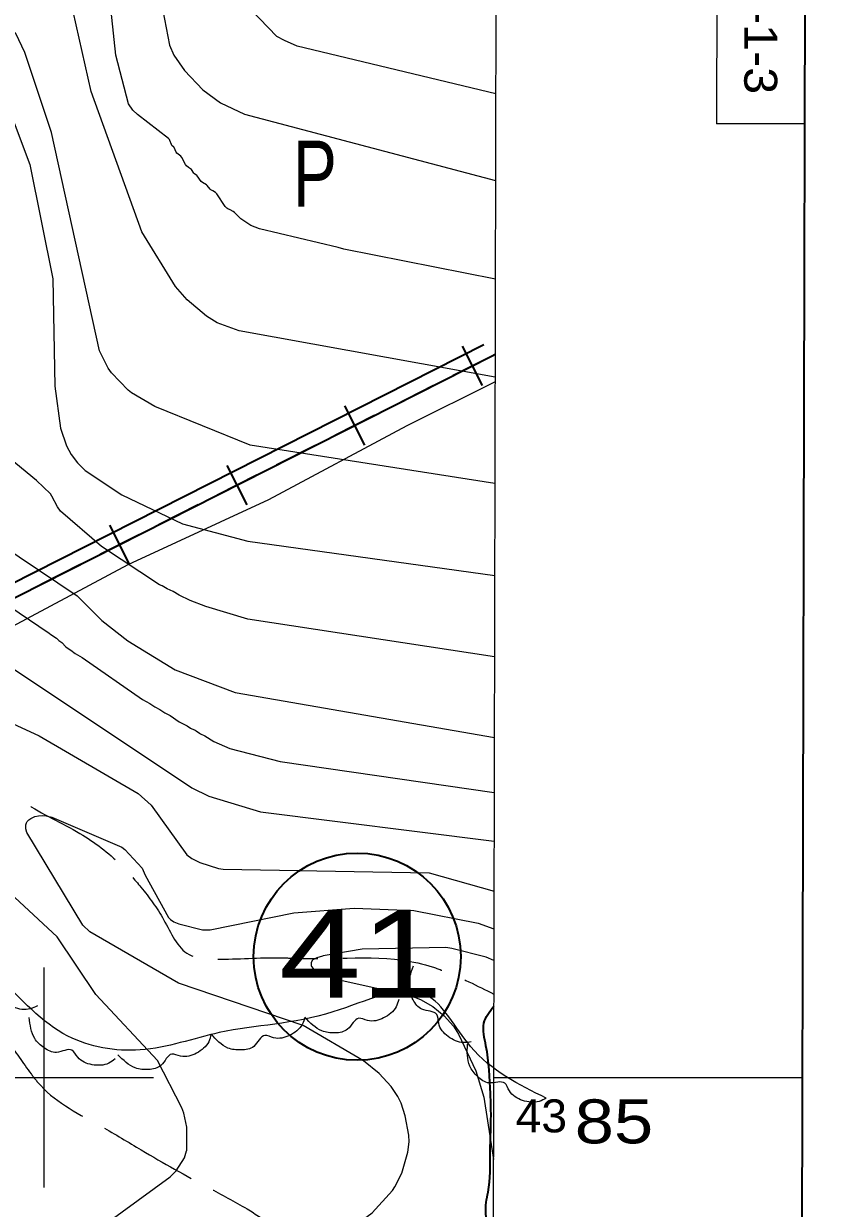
# Model space of a CAD drawing. Extents: x 480269 to 484877, y 4383588 to 4386804.
# Drawn here: x 483995.4 to 484176.2, y 4384970.2 to 4385239.6 of the extents above; entities that cross this region are included whole.
import ezdxf
from ezdxf.enums import TextEntityAlignment as Align

# ---------------------------------------------------------------- set-up
doc = ezdxf.new("R2010")
doc.units = 0
doc.header["$LTSCALE"] = 3.8
doc.linetypes.add('DOTTED', pattern=[1.5, 0.3, -1.2])
doc.linetypes.add('LONG_DASHED', pattern=[7.5, 6, -1.5])
for name, color, linetype, lineweight in [('1', 7, 'Continuous', 13), ('13', 7, 'Continuous', 25), ('2', 7, 'DOTTED', 13), ('27', 7, 'Continuous', 25), ('34', 7, 'Continuous', 35), ('38', 7, 'Continuous', 25), ('51', 7, 'Continuous', 13), ('6', 7, 'Continuous', 35), ('8', 7, 'Continuous', 25), ('9', 7, 'Continuous', 13)]:
    doc.layers.add(name, color=color, linetype=linetype, lineweight=lineweight)
doc.layers.add('31', color=7, linetype='Continuous')

msp = doc.modelspace()

# ---------------------------------------------------------------- linework, layer by layer
at = {"layer": '1'}
for p, q in [((484173.1, 4385216.78), (484153.1, 4385216.82)), ((484000, 4385025), (484000, 4384975)), ((483975, 4385000), (484025, 4385000)), ((484102.37, 4385000), (484172.58, 4385000))]:
    msp.add_line(p, q, dxfattribs=at)
at = {"layer": '1', "lineweight": 35}
msp.add_lwpolyline([(480458.83, 4386528.21), (484176.23, 4386519.28), (484170.33, 4384064.28), (480452.93, 4384073.22)], close=True, dxfattribs=at)
at = {"layer": '1'}
msp.add_lwpolyline([(480529.1, 4386456.6), (484105.5, 4386448.1), (484100.5, 4384135.8), (480523.1, 4384144.4)], close=True, dxfattribs=at)
msp.add_lwpolyline([(484173.46, 4385366.78), (484153.46, 4385366.82), (484153.1, 4385216.82)], dxfattribs=at)
at = {"layer": '27'}
for points in [[(484114.34, 4384995.29), (484097.11, 4385007.04), (484086.93, 4385018.79), (484065.79, 4385014.87), (484039.96, 4385010.17), (484021.95, 4385006.26), (484005.51, 4385009.39), (483989.85, 4385022.71), (483953.05, 4385049.34), (483919.38, 4385069.7), (483866.14, 4385090.85), (483825.42, 4385101.82), (483759.65, 4385127.67), (483723.64, 4385129.24)], [(483998.56, 4385016.28), (483996.93, 4385015.58), (483993.15, 4385015.96), (483990.25, 4385018.24), (483989.27, 4385020.04), (483985.72, 4385020.22), (483983.15, 4385021.74), (483981.43, 4385024.23), (483981.11, 4385029.18)], [(484097.29, 4385008.11), (484095.53, 4385007.9), (484092.01, 4385009.31), (484089.86, 4385012.32), (484089.43, 4385014.32), (484086.06, 4385015.48), (484084.03, 4385017.66), (484083.07, 4385020.53), (484084.15, 4385025.37)], [(484080.78, 4385017.7), (484080.17, 4385016.03), (484077.33, 4385013.52), (484073.68, 4385012.94), (484071.7, 4385013.45), (484069.15, 4385010.97), (484066.29, 4385010.12), (484063.3, 4385010.55), (484059.45, 4385013.68)], [(484016.27, 4385004.21), (484014.79, 4385003.22), (484011.01, 4385002.89), (484007.74, 4385004.59), (484006.44, 4385006.18), (484002.92, 4385005.69), (484000.11, 4385006.71), (483997.96, 4385008.83), (483996.72, 4385013.64)], [(484059.44, 4385013.72), (484058.83, 4385012.05), (484055.97, 4385009.56), (484052.32, 4385009.01), (484050.34, 4385009.53), (484047.78, 4385007.06), (484044.91, 4385006.23), (484041.92, 4385006.68), (484038.09, 4385009.84)], [(484038.1, 4385009.8), (484037.55, 4385008.11), (484034.78, 4385005.52), (484031.15, 4385004.84), (484029.15, 4385005.29), (484026.68, 4385002.73), (484023.84, 4385001.8), (484020.84, 4385002.15), (484016.9, 4385005.16)], [(484114.34, 4384995.29), (484112.73, 4384994.53), (484108.95, 4384994.77), (484105.96, 4384996.94), (484104.91, 4384998.7), (484101.36, 4384998.74), (484098.74, 4385000.17), (484096.93, 4385002.59), (484096.42, 4385007.52)]]:
    msp.add_spline(points, degree=3, dxfattribs=at)
at = {"layer": '34'}
for p, q in [((484102, 4385164), (484093.09, 4385159.49)), ((484099.81, 4385157.29), (484095.29, 4385166.21)), ((484102.72, 4385164.38), (484102, 4385164)), ((484102.72, 4385164.38), (484102, 4385164)), ((484088.63, 4385157.23), (484079.7, 4385152.71)), ((484073.05, 4385143.74), (484068.53, 4385152.66)), ((484075.25, 4385150.46), (484066.33, 4385145.94)), ((484061.87, 4385143.68), (484052.95, 4385139.17)), ((484046.29, 4385130.19), (484041.78, 4385139.11)), ((484048.5, 4385136.91), (484039.57, 4385132.39)), ((484035.11, 4385130.14), (484026.19, 4385125.62)), ((484019.54, 4385116.65), (484015.02, 4385125.57)), ((484021.74, 4385123.37), (484012.82, 4385118.85)), ((484008.36, 4385116.59), (483999.44, 4385112.07))]:
    msp.add_line(p, q, dxfattribs=at)
for points in [[(484100.12, 4385166.55), (483464.12, 4384844.55), (483456.6, 4384851.12)], [(484100.12, 4385166.55), (483464.12, 4384844.55), (483456.6, 4384851.12)], [(484102, 4385164), (483466, 4384842), (483458.48, 4384848.57)]]:
    msp.add_lwpolyline(points, dxfattribs=at)
at = {"layer": '38', "linetype": 'LONG_DASHED'}
for points in [[(483942.39, 4385122.34), (483952.45, 4385095.91), (483958.21, 4385088.21), (483962.69, 4385083.26), (483973.19, 4385074.99), (483980.96, 4385070.43), (483992.37, 4385064.77), (483995.68, 4385062.46), (484008.26, 4385055.45), (484017.51, 4385048.36), (484022.13, 4385043.23), (484027.29, 4385035.86), (484033.07, 4385027.94), (484039.2, 4385026.88), (484053.86, 4385027.2), (484058.16, 4385027.05), (484086.84, 4385025.6), (484090.95, 4385024.22), (484102.41, 4385018.95)], [(483895.65, 4385049.41), (483901.31, 4385046.22), (483904.97, 4385044), (483908.38, 4385043.58), (483917.3, 4385045.07), (483924.03, 4385045.27), (483935.07, 4385044.92), (483947.94, 4385042.69), (483964.34, 4385037.18), (483972.2, 4385033.41), (483980.56, 4385025.17), (483986.43, 4385015.59), (483991.76, 4385008.34), (483997.14, 4385000.8), (483999.32, 4384998.13), (484013.2, 4384988.81), (484022.21, 4384983.5), (484037.49, 4384974.93), (484046.27, 4384970.1), (484052.18, 4384966.26), (484063.24, 4384958.28), (484072.05, 4384951.59)]]:
    msp.add_spline(points, degree=3, dxfattribs=at)
at = {"layer": '51'}
msp.add_lwpolyline([(484102.71, 4385158.17), (484082.61, 4385148.15), (484051.15, 4385131.29), (484019.11, 4385116.52), (483992.79, 4385102.45), (483964.38, 4385087.36), (483957.17, 4385084.5)], dxfattribs=at)
at = {"layer": '6'}
msp.add_circle((484071.32, 4385027.45), 23.55, dxfattribs=at)
msp.add_spline([(484072.71, 4384951.59), (484076.5, 4384951.46), (484085.91, 4384953.29), (484092.76, 4384955.65), (484097.86, 4384958.35), (484100.69, 4384966.27), (484100.68, 4384971.57), (484101.12, 4384973.91), (484101.59, 4384983.01), (484101.76, 4384992.72), (484101.64, 4384996.31), (484100.61, 4385007.16), (484100.17, 4385012.34), (484102.4, 4385016.18)], degree=3, dxfattribs=at)
at = {"layer": '8'}
for points in [[(484102.66, 4385135.05), (484046.95, 4385143.74), (484025.31, 4385152.49), (484019.95, 4385155.66), (484019.19, 4385156.21), (484015.46, 4385160.21), (484014.7, 4385161.26), (484012.69, 4385165.2), (484001.76, 4385214.82), (483995.69, 4385233.03), (483993.63, 4385237.36), (483992.77, 4385238.34), (483990.76, 4385239.88)], [(483967.81, 4385109.7), (484033.71, 4385065.86), (484037.56, 4385063.92), (484049.36, 4385060.39), (484102.48, 4385053.67)]]:
    msp.add_lwpolyline(points, dxfattribs=at)
at = {"layer": '9'}
msp.add_line((484102.76, 4385181.49), (484068.3, 4385188.32), dxfattribs=at)
for points in [[(484102.71, 4385159.22), (484044.49, 4385169.71), (484039.47, 4385171.58), (484037.02, 4385173.05), (484032.68, 4385176.75), (484029.98, 4385179.78), (484022.32, 4385192.2), (484010.83, 4385224.15), (484003.97, 4385254.56)], [(484068.3, 4385188.32), (484066.96, 4385188.71), (484049.1, 4385192.91), (484047.12, 4385193.69), (484044.89, 4385195.16), (484043.4, 4385196.65), (484043.14, 4385196.85), (484042.42, 4385197.27), (484041.91, 4385197.47), (484041.66, 4385197.62), (484041.29, 4385197.98), (484039.39, 4385200.85), (484039.07, 4385201.21), (484038.52, 4385201.57), (484038.05, 4385201.8), (484037.84, 4385201.97), (484037.23, 4385202.75), (484037.02, 4385202.92), (484036.1, 4385203.44), (484035.84, 4385203.68), (484034.93, 4385204.95), (484034.84, 4385205.05), (484034.31, 4385205.43), (484034.18, 4385205.59), (484033.61, 4385206.41), (484033.41, 4385206.59), (484032.98, 4385206.86), (484032.51, 4385207.21), (484032.27, 4385207.53), (484031.42, 4385209.14), (484031.18, 4385209.47), (484030.32, 4385210.14), (484030.14, 4385210.35), (484029.65, 4385211.37), (484029.6, 4385211.45), (484029.17, 4385211.88), (484029.07, 4385212.07), (484028.71, 4385213.01), (484028.6, 4385213.2), (484028.39, 4385213.42), (484021.35, 4385218.89), (484020.32, 4385219.89), (484019.28, 4385221.31), (484016.42, 4385232.39), (484014.08, 4385254.57)], [(484102.85, 4385223.6), (484057.68, 4385234.48), (484054.81, 4385235.74), (484053.02, 4385236.67), (484039.17, 4385251.11)], [(484025.95, 4385248.56), (484028.62, 4385234.66), (484029.59, 4385232.37), (484032.04, 4385228.88), (484036.21, 4385224.54), (484040.25, 4385221.56), (484045.66, 4385218.99), (484102.81, 4385203.94)], [(483992.6, 4385218.8), (483996.84, 4385207.58), (484002.1, 4385181.53), (484002.52, 4385157.16), (484003.83, 4385147.59), (484005.2, 4385143.6), (484006.29, 4385141.63), (484007.72, 4385139.72), (484009.42, 4385138), (484017.75, 4385132.46), (484031.55, 4385125.87), (484046.45, 4385121.91), (484102.62, 4385114.11)], [(484102.58, 4385095.62), (484046.46, 4385104.16), (484036.88, 4385107.09), (484033.34, 4385108.45), (484030.84, 4385109.65), (484029.45, 4385110.48), (484028.06, 4385111.04), (484026.95, 4385111.73), (484026.33, 4385112), (484013.18, 4385120.72), (484003.81, 4385128.72), (484003.13, 4385129.75), (484001.89, 4385132.13), (484001.54, 4385132.68), (483998.4, 4385135.7), (483992.36, 4385140.64)], [(483985.53, 4385124.27), (484007.59, 4385109.51), (484013.24, 4385103.86), (484019.18, 4385099.22), (484029.89, 4385092.63), (484043.53, 4385087.47), (484102.54, 4385077.28)], [(483969.62, 4385122.4), (484001.28, 4385100.96), (484001.6, 4385100.7), (484002.88, 4385099.87), (484003.46, 4385099.32), (484004.13, 4385098.84), (484005.07, 4385097.86), (484005.31, 4385097.66)], [(483941.08, 4385098.8), (483941.36, 4385098.99), (483941.92, 4385099.2), (483942.73, 4385099.4), (483942.86, 4385099.42), (483944.07, 4385099.51), (483945.44, 4385099.46), (483945.47, 4385099.47), (483947.42, 4385099.17), (483951.55, 4385098.03), (483951.57, 4385098.03), (483975.99, 4385088.91), (483982.84, 4385085.08), (483999, 4385077.66), (484021.46, 4385064.54), (484024.45, 4385061.9), (484032.59, 4385050.6), (484033.74, 4385049.77), (484035.54, 4385048.88), (484039.76, 4385047.5), (484040.84, 4385047.35), (484087.73, 4385046.53), (484102.46, 4385042.34)], [(484004.15, 4384959.43), (484028.77, 4384977.43), (484030.13, 4384978.73), (484032.05, 4384981.75), (484032.51, 4384983.29), (484032.54, 4384983.31), (484032.57, 4384988.65), (484031.89, 4384991.86), (484031.45, 4384993.1), (484025.86, 4385003.85), (484011.9, 4385018.81), (484003.09, 4385031.95), (483949.37, 4385081.77), (483947.94, 4385083.28), (483944.1, 4385088.45), (483940.57, 4385094.75), (483940.17, 4385096), (483940.15, 4385096.18), (483940.12, 4385097), (483940.19, 4385097.53), (483940.29, 4385097.83), (483940.63, 4385098.35), (483941.08, 4385098.8)], [(484005.31, 4385097.66), (484006.21, 4385097.1), (484007.14, 4385096.35), (484008.72, 4385095.45), (484022.48, 4385085.94), (484024.14, 4385085.02), (484025.3, 4385084.25), (484026.46, 4385083.64), (484027.53, 4385082.9), (484028.76, 4385082.25), (484030.83, 4385080.82), (484032.64, 4385079.94), (484033.42, 4385079.4), (484033.53, 4385079.34), (484034.49, 4385078.91), (484034.71, 4385078.79), (484035.43, 4385078.24), (484035.66, 4385078.11), (484036.66, 4385077.69), (484038.69, 4385076.38), (484042.38, 4385074.79), (484053.83, 4385071.81), (484102.51, 4385064.79)], [(484083.12, 4384985.37), (484083.06, 4384986.85), (484082.27, 4384991.23), (484081.32, 4384994.17), (484080.58, 4384995.65), (484079.02, 4384997.94), (484076.32, 4385000.88), (484072.76, 4385003.75), (484059.02, 4385011.81), (484030.65, 4385021.43), (484010.53, 4385033.11), (484008.9, 4385034.63), (483996.18, 4385055.68), (483995.97, 4385056.49), (483995.92, 4385056.87), (483995.95, 4385057.44), (483996.12, 4385057.9), (483996.26, 4385058.14), (483996.61, 4385058.54), (483997.06, 4385058.88), (483997.35, 4385059.04), (483997.96, 4385059.28), (483998.83, 4385059.46), (483999.78, 4385059.51), (484000.56, 4385059.45), (484001.82, 4385059.2), (484017.8, 4385052.37), (484018.49, 4385051.78), (484022.43, 4385047.53), (484023.11, 4385046.01), (484028.43, 4385036.33), (484028.84, 4385035.93), (484029.6, 4385035.38), (484030.73, 4385034.89), (484036.16, 4385033.54), (484037.9, 4385033.54), (484056.94, 4385037.42), (484070.67, 4385038.5), (484084.21, 4385037.95), (484098.83, 4385035.03), (484102.44, 4385033.78)], [(484102.43, 4385026.56), (484100.65, 4385027.35), (484092.87, 4385029.32), (484091.46, 4385029.55), (484072.46, 4385029.13), (484063.57, 4385027.62), (484063.43, 4385027.58), (484062.17, 4385027.16), (484061.38, 4385026.81), (484061.22, 4385026.69), (484061.09, 4385026.57), (484060.82, 4385026.05), (484060.84, 4385025.5), (484060.88, 4385025.36), (484060.95, 4385025.22), (484061.32, 4385024.76), (484061.97, 4385024.15), (484062.07, 4385024.08), (484063.15, 4385023.53), (484063.18, 4385023.52), (484063.19, 4385023.51), (484063.2, 4385023.49), (484066.92, 4385022.23), (484083.62, 4385018.54), (484085.7, 4385017.73), (484088.5, 4385016.12), (484091.11, 4385014.03), (484093.26, 4385011.64), (484094.37, 4385009.81), (484098.29, 4385001.46), (484100.1, 4384995.49), (484102.33, 4384981.36)], [(483843.12, 4384882.24), (483862.67, 4384892.55), (483872.76, 4384900.16), (483900.45, 4384915.33), (483903.58, 4384916.33), (483924.79, 4384920.99), (483987.72, 4384924.49), (483993.76, 4384926.67), (484057.08, 4384956.26), (484074.71, 4384969.24), (484079.32, 4384974.31), (484079.87, 4384975.12), (484081.46, 4384978.19), (484082.83, 4384982.99), (484083.12, 4384985.37)]]:
    msp.add_lwpolyline(points, dxfattribs=at)

# ---------------------------------------------------------------- texts
at = {"layer": '13', "width": 1.25}
msp.add_text('41', height=20, dxfattribs=at).set_placement((484072.15, 4385018.14), align=Align.CENTER)
at = {"layer": '2', "width": 1.1}
msp.add_text('699-1-3', height=7.5, rotation=269.862, dxfattribs=at).set_placement((484159.46, 4385261.56))
at = {"layer": '2'}
for s, height, width, p in [('43', 7.5, 1.05, (484107.36, 4384987.5)), ('85  ', 10, 1.2, (484120.81, 4384985))]:
    msp.add_text(s, height=height, dxfattribs=dict(at, width=width)).set_placement(p)
at = {"layer": '31', "width": 0.75}
msp.add_text('P', height=15, dxfattribs=at).set_placement((484061.7, 4385197.96), align=Align.CENTER)

doc.saveas('drawing.dxf')
